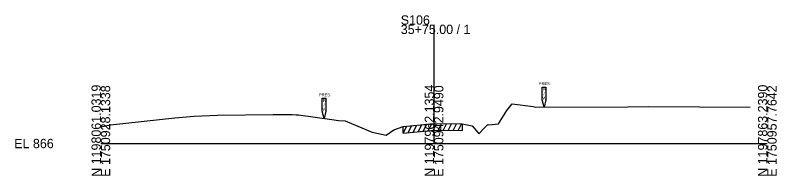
# Model space of a CAD drawing. Extents: x -26 to 1203, y -10 to 19527.
# Drawn here: x 974.3 to 1202.8, y 1490.3 to 1538.6 of the extents above; entities that cross this region are included whole.
import ezdxf

# ---------------------------------------------------------------- set-up
doc = ezdxf.new("R2010")
doc.units = 0
for name, color, linetype in [('RD_GPK_XS_Cell', 7, 'Continuous'), ('RD_XS_ExGround', 7, 'Continuous'), ('RD_XS_ExPaveRet', 7, 'Continuous'), ('RD_XS_ExRW', 7, 'Continuous'), ('RD_XS_TX_Elev_EX', 7, 'Continuous')]:
    doc.layers.add(name, color=color, linetype=linetype)

msp = doc.modelspace()

# ---------------------------------------------------------------- linework, layer by layer
at = {"layer": 'RD_GPK_XS_Cell'}
for p, q in [((1100, 1500), (1100, 1535.71)), ((1000, 1500), (1100, 1500)), ((1100, 1500), (1200, 1500))]:
    msp.add_line(p, q, dxfattribs=at)
at = {"layer": 'RD_XS_ExGround'}
msp.add_lwpolyline([(1000, 1505.02), (1002.93, 1505.6), (1022.24, 1507.77), (1027.99, 1508.21), (1034.98, 1508.54), (1051.74, 1508.69), (1053.51, 1508.68), (1057.42, 1508.74), (1058.61, 1508.67), (1059.34, 1508.64), (1069.36, 1507.23), (1071.31, 1506.9), (1073.34, 1506.82), (1077.16, 1505.22), (1081.46, 1503.42), (1085.66, 1502.52), (1087.92, 1504.16), (1090.75, 1505.15), (1099.07, 1505.89), (1099.8, 1505.96), (1100.5, 1505.97), (1108.38, 1505.88), (1111.43, 1505.34), (1113.12, 1503.31), (1113.46, 1502.89), (1115.15, 1504.68), (1116.15, 1505.68), (1116.46, 1505.66), (1119.32, 1505.96), (1121.85, 1509.94), (1123.46, 1511.9), (1129.75, 1511.11), (1130.51, 1510.9), (1158.13, 1511.02), (1164.46, 1511.14), (1194.87, 1510.92)], dxfattribs=at)
at = {"layer": 'RD_XS_ExPaveRet'}
for p, q in [((1090.75, 1503.15), (1091.8, 1505.24)), ((1090.75, 1503.15), (1090.75, 1505.15)), ((1090.75, 1503.15), (1099.07, 1503.89)), ((1092.25, 1503.28), (1093.3, 1505.38)), ((1093.75, 1503.42), (1094.8, 1505.51)), ((1095.25, 1503.55), (1096.3, 1505.64)), ((1096.75, 1503.68), (1097.8, 1505.78)), ((1098.25, 1503.82), (1099.3, 1505.91)), ((1099.07, 1503.89), (1099.8, 1503.96)), ((1099.75, 1503.95), (1100.75, 1505.96)), ((1099.8, 1503.96), (1100.5, 1503.97)), ((1100.5, 1503.97), (1108.38, 1503.88)), ((1101.25, 1503.96), (1102.25, 1505.95)), ((1102.75, 1503.94), (1103.75, 1505.93)), ((1104.25, 1503.93), (1105.25, 1505.92)), ((1105.75, 1503.91), (1106.75, 1505.9)), ((1107.25, 1503.9), (1108.25, 1505.89)), ((1108.38, 1505.88), (1108.38, 1503.88))]:
    msp.add_line(p, q, dxfattribs=at)
at = {"layer": 'RD_XS_ExRW'}
for points in [[(1132.45, 1516.93), (1133.55, 1516.93), (1133.55, 1513.1), (1133, 1510.91), (1132.45, 1513.1)], [(1066.45, 1513.58), (1067.55, 1513.58), (1067.55, 1509.75), (1067, 1507.56), (1066.45, 1509.75)]]:
    msp.add_lwpolyline(points, close=True, dxfattribs=at)

# ---------------------------------------------------------------- texts
at = {"layer": 'RD_GPK_XS_Cell'}
for s, p in [('S106', (1090, 1535.71)), ('35+75.00 / 1', (1090, 1532.91)), ('EL 866', (974, 1498.6))]:
    msp.add_text(s, height=2.8, dxfattribs=at).set_placement(p)
for s, p in [('N 1198061.0319', (1000, 1490)), ('N 1197962.1354', (1100, 1490)), ('N 1197863.2390', (1200, 1490)), ('E 1750928.1338', (1002.8, 1490)), ('E 1750942.9490', (1102.8, 1490)), ('E 1750957.7642', (1202.8, 1490))]:
    msp.add_text(s, height=2.8, rotation=90, dxfattribs=at).set_placement(p)
at = {"layer": 'RD_XS_ExRW'}
for s, p in [('PRES.', (1131.45, 1517.55)), ('R', (1132.71, 1515.84)), ('/', (1132.83, 1514.52)), ('PRES.', (1065.45, 1514.21)), ('R', (1066.71, 1512.49)), ('W', (1132.53, 1513.21)), ('W', (1066.53, 1509.86)), ('/', (1066.83, 1511.18))]:
    msp.add_text(s, height=0.875, dxfattribs=at).set_placement(p)
at = {"layer": 'RD_XS_TX_Elev_EX'}
msp.add_text('868.98', height=0.0975, rotation=90, dxfattribs=at).set_placement((1100.1, 1505.96))

doc.saveas('drawing.dxf')
